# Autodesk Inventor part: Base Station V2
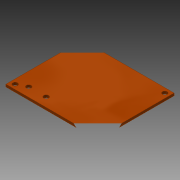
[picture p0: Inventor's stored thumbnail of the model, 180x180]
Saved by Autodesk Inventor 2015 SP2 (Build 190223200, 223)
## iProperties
Created: 2014-11
Part Number: Base Station V2
Material: Phenolharz
Document SubType Name: Modeling
Designer: AndreR
Mass: 6.51745 g
Surface Area: 63.52 cm^2
Volume: 4.72279 cm^3
Density: 1.38 g/cm^3
Appearance: Glatt - hellorange
Author: AndreR
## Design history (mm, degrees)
sketch "Skizze1"
  geometry: L1 (-30, 25)-(30, 25); L2 (30, 25)-(30, -25); L3 (30, -25)-(-30, -25); L4 (-30, -25)-(-30, 25); L5 (0, 35)-(0, -35) reference; L6 (-42, 0)-(42, 0) reference; 1 further point
  constraints: 8 end point, 2 parallel, 1 horizontal, 1 perpendicular, 2 other
  dimensions: "d0" = 50 distance of L3.end L1.start; "d1" = 60 distance of L1.start L1.end
extrude "Extrusion1" new body sketch "Skizze1" distance "d2" = 1.6; taper "d3" = 0 deg
sketch "Skizze2"
  geometry: L1 (-30, 25)-(30, 25) reference; L2 (-30, -25)-(-30, 25) reference; 2 further points
  dimensions: "d4" = 3 distance from line of L1 point (-27, 22); "d5" = 3 distance from line of point (-27, 22) L2
hole "Bohrung1" sketch "Skizze2" at (-27, 22) diameter "d6" = 3.2; stored, may be unused: countersink angle "d10" = 90 deg, drill point angle "d12" = 118 deg; dims "d7" = 6, "d8" = 4, "d9" = 2, "d11" = 8
pattern_linear "Rechteckige Anordnung1" dims "d15" = 54, "d18" = 44
sketch "Skizze3"
  geometry: L1 (-30, -25)-(-30, 25) reference; L2 (30, -25)-(-30, -25) reference; 3 further points
  dimensions: "d19" = 6 distance from line of point (-21.1, -19) L2; "d20" = 8.9 distance from line of point (-21.1, -19) L1; "d21" = 20.3 distance from line of L1 point (-9.7, -19); "d22" = 6 distance from line of point (-9.7, -19) L2
hole "Bohrung2" sketch "Skizze3" at (-21.1, -19), (-9.7, -19) diameter "d23" = 3.2; stored, may be unused: countersink angle "d27" = 90 deg, drill point angle "d29" = 118 deg; dims "d24" = 6, "d25" = 4, "d26" = 2, "d28" = 8
node "Volumenkörper1"
